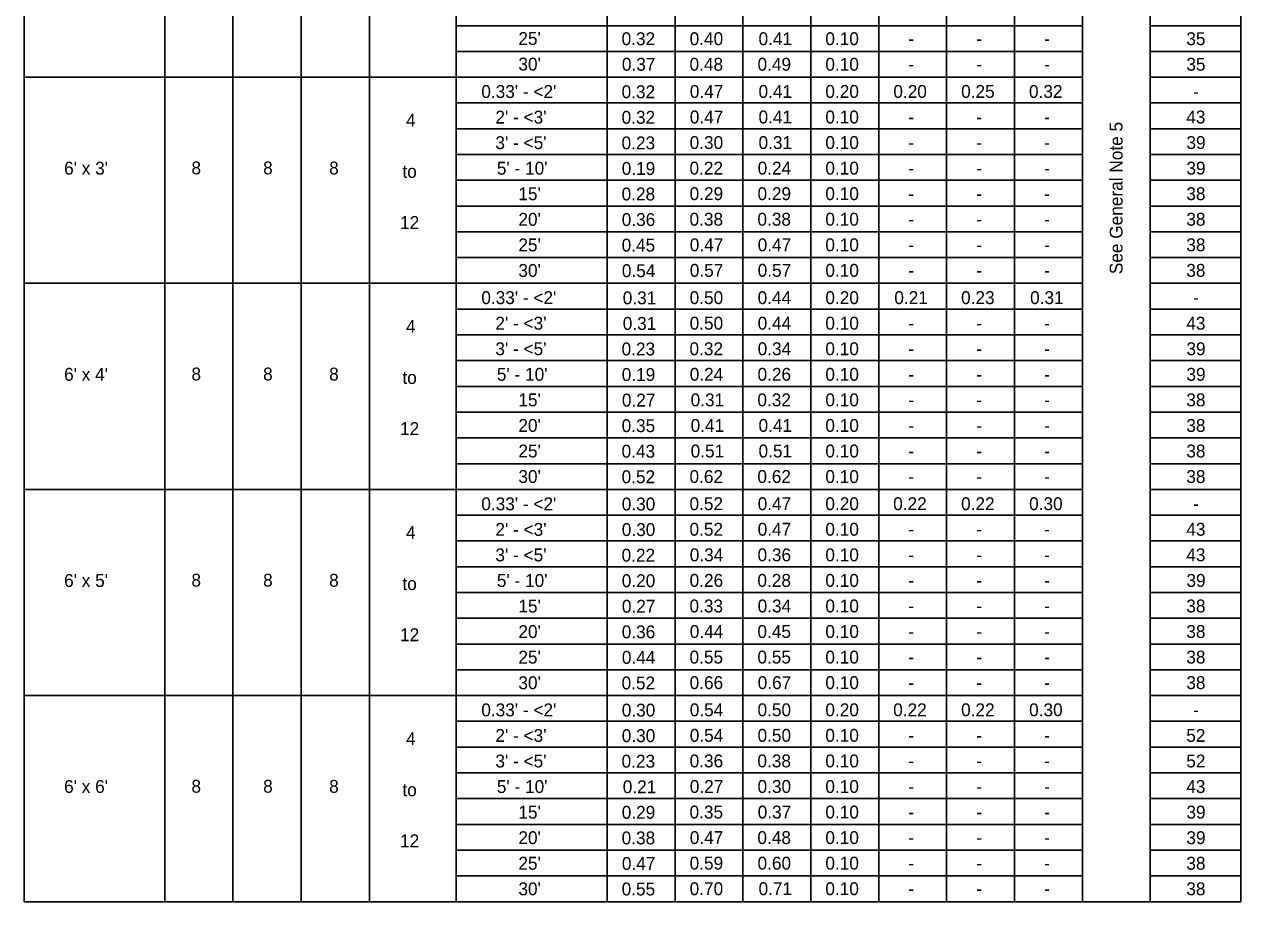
# Model space of a CAD drawing. Extents: x 10340.93 to 10343.14, y 76399.51 to 76400.59.
# Drawn here: x 10341.579 to 10342.173, y 76399.724 to 76400.153 of the extents above; entities that cross this region are included whole.
import ezdxf

# ---------------------------------------------------------------- set-up
doc = ezdxf.new("R2010")
doc.units = 0
doc.layers.add('AdhocPoint_dp', color=7, linetype='Continuous')
doc.layers.add('PlotBorder_dp', color=7, linetype='Continuous')

msp = doc.modelspace()

# ---------------------------------------------------------------- linework, layer by layer
at = {"layer": 'PlotBorder_dp'}
for p, q in [((10341.57868, 76400.49971), (10341.57868, 76399.72389)), ((10342.17342, 76400.49971), (10342.17342, 76399.72389)), ((10341.64732, 76400.47984), (10341.64732, 76399.72389)), ((10341.78976, 76400.47984), (10341.78976, 76399.72389)), ((10341.86364, 76400.47984), (10341.86364, 76399.72389)), ((10342.12923, 76400.47984), (10342.12923, 76399.72389)), ((10341.68068, 76400.46724), (10341.68068, 76399.72389)), ((10341.71404, 76400.46724), (10341.71404, 76399.72389)), ((10341.7474, 76400.46724), (10341.7474, 76399.72389)), ((10341.89684, 76400.44209), (10341.89684, 76399.72389)), ((10341.93004, 76400.44209), (10341.93004, 76399.72389)), ((10341.96324, 76400.44209), (10341.96324, 76399.72389)), ((10341.99644, 76400.44209), (10341.99644, 76399.72389)), ((10342.02963, 76400.44209), (10342.02963, 76399.72389)), ((10342.02963, 76400.44209), (10342.02963, 76399.72389)), ((10342.06283, 76400.44209), (10342.06283, 76399.72389)), ((10342.09603, 76400.44209), (10342.09603, 76399.72389)), ((10341.78976, 76400.15229), (10342.09603, 76400.15229)), ((10342.12923, 76400.15229), (10342.17342, 76400.15229)), ((10341.78976, 76400.13969), (10342.09603, 76400.13969)), ((10342.12923, 76400.13969), (10342.17342, 76400.13969)), ((10341.57868, 76400.12709), (10342.09603, 76400.12709)), ((10342.12923, 76400.12709), (10342.17342, 76400.12709)), ((10341.78976, 76400.11449), (10342.09603, 76400.11449)), ((10342.12923, 76400.11449), (10342.17342, 76400.11449)), ((10341.78976, 76400.10189), (10342.09603, 76400.10189)), ((10342.12923, 76400.10189), (10342.17342, 76400.10189)), ((10341.78976, 76400.08929), (10342.09603, 76400.08929)), ((10342.12923, 76400.08929), (10342.17342, 76400.08929)), ((10341.78976, 76400.07669), (10342.09603, 76400.07669)), ((10342.12923, 76400.07669), (10342.17342, 76400.07669)), ((10341.78976, 76400.06409), (10342.09603, 76400.06409)), ((10342.12923, 76400.06409), (10342.17342, 76400.06409)), ((10341.78976, 76400.05149), (10342.09603, 76400.05149)), ((10342.12923, 76400.05149), (10342.17342, 76400.05149)), ((10341.78976, 76400.03889), (10342.09603, 76400.03889)), ((10342.12923, 76400.03889), (10342.17342, 76400.03889)), ((10341.57868, 76400.02629), (10342.09603, 76400.02629)), ((10341.79037, 76400.02629), (10341.86254, 76400.02629)), ((10342.12923, 76400.02629), (10342.17342, 76400.02629)), ((10341.78976, 76400.01369), (10342.09603, 76400.01369)), ((10342.12923, 76400.01369), (10342.17342, 76400.01369)), ((10341.78976, 76400.00109), (10342.09603, 76400.00109)), ((10342.12923, 76400.00109), (10342.17342, 76400.00109)), ((10341.78976, 76399.98849), (10342.09603, 76399.98849)), ((10342.12923, 76399.98849), (10342.17342, 76399.98849)), ((10341.78976, 76399.97589), (10342.09603, 76399.97589)), ((10342.12923, 76399.97589), (10342.17342, 76399.97589)), ((10341.78976, 76399.96329), (10342.09603, 76399.96329)), ((10342.12923, 76399.96329), (10342.17342, 76399.96329)), ((10341.78976, 76399.95069), (10342.09603, 76399.95069)), ((10342.12923, 76399.95069), (10342.17342, 76399.95069)), ((10341.78976, 76399.93809), (10342.09603, 76399.93809)), ((10342.12923, 76399.93809), (10342.17342, 76399.93809)), ((10341.57868, 76399.92549), (10342.09603, 76399.92549)), ((10341.79037, 76399.92549), (10341.86254, 76399.92549)), ((10341.79037, 76399.92549), (10341.86254, 76399.92549)), ((10342.12923, 76399.92549), (10342.17342, 76399.92549)), ((10341.78976, 76399.91289), (10342.09603, 76399.91289)), ((10342.12923, 76399.91289), (10342.17342, 76399.91289)), ((10341.78976, 76399.90029), (10342.09603, 76399.90029)), ((10342.12923, 76399.90029), (10342.17342, 76399.90029)), ((10341.78976, 76399.88769), (10342.09603, 76399.88769)), ((10342.12923, 76399.88769), (10342.17342, 76399.88769)), ((10341.78976, 76399.87509), (10342.09603, 76399.87509)), ((10342.12923, 76399.87509), (10342.17342, 76399.87509)), ((10341.78976, 76399.86249), (10342.09603, 76399.86249)), ((10342.12923, 76399.86249), (10342.17342, 76399.86249)), ((10341.78976, 76399.84989), (10342.09603, 76399.84989)), ((10342.12923, 76399.84989), (10342.17342, 76399.84989)), ((10341.78976, 76399.83729), (10342.09603, 76399.83729)), ((10342.12923, 76399.83729), (10342.17342, 76399.83729)), ((10341.57868, 76399.82469), (10342.09603, 76399.82469)), ((10341.79037, 76399.82469), (10341.86254, 76399.82469)), ((10341.79037, 76399.82469), (10341.86254, 76399.82469)), ((10341.79037, 76399.82469), (10341.86254, 76399.82469)), ((10342.12923, 76399.82469), (10342.17342, 76399.82469)), ((10341.78976, 76399.81209), (10342.09603, 76399.81209)), ((10342.12923, 76399.81209), (10342.17342, 76399.81209)), ((10341.78976, 76399.79949), (10342.09603, 76399.79949)), ((10342.12923, 76399.79949), (10342.17342, 76399.79949)), ((10341.78976, 76399.78689), (10342.09603, 76399.78689)), ((10342.12923, 76399.78689), (10342.17342, 76399.78689)), ((10341.78976, 76399.77429), (10342.09603, 76399.77429)), ((10342.12923, 76399.77429), (10342.17342, 76399.77429)), ((10341.78976, 76399.76169), (10342.09603, 76399.76169)), ((10342.12923, 76399.76169), (10342.17342, 76399.76169)), ((10341.78976, 76399.74909), (10342.09603, 76399.74909)), ((10342.12923, 76399.74909), (10342.17342, 76399.74909)), ((10341.78976, 76399.73649), (10342.09603, 76399.73649)), ((10342.12923, 76399.73649), (10342.17342, 76399.73649)), ((10341.57868, 76399.72389), (10342.17342, 76399.72389)), ((10341.79037, 76399.72389), (10341.86254, 76399.72389))]:
    msp.add_line(p, q, dxfattribs=at)

# ---------------------------------------------------------------- texts
at = {"layer": 'AdhocPoint_dp'}
msp.add_text('See General Note 5', height=0.0063, rotation=90, dxfattribs=at).set_placement((10342.11568, 76400.03076))
at = {"layer": 'PlotBorder_dp'}
for s, p in [("25'", (10341.82025, 76400.14286)), ('0.32', (10341.87072, 76400.14276)), ('0.40', (10341.90399, 76400.14276)), ('0.41', (10341.93768, 76400.14276)), ('0.10', (10341.97035, 76400.14276)), ('-', (10342.01091, 76400.14276)), ('-', (10342.04412, 76400.14276)), ('-', (10342.0773, 76400.14276)), ('35', (10342.14685, 76400.14276)), ("30'", (10341.82025, 76400.13036)), ('0.37', (10341.87086, 76400.13026)), ('0.48', (10341.90393, 76400.13026)), ('0.49', (10341.93718, 76400.13026)), ('0.10', (10341.97035, 76400.13026)), ('-', (10342.01091, 76400.13026)), ('-', (10342.04412, 76400.13026)), ('-', (10342.0773, 76400.13026)), ('35', (10342.14685, 76400.13026)), ("0.33' - <2'", (10341.80212, 76400.11693)), ('0.32', (10341.87072, 76400.11682)), ('0.47', (10341.90406, 76400.11698)), ('0.41', (10341.93768, 76400.11698)), ('0.20', (10341.97035, 76400.11698)), ('0.20', (10342.00358, 76400.11698)), ('0.25', (10342.03674, 76400.11698)), ('0.32', (10342.0699, 76400.11698)), ('-', (10342.15015, 76400.11698)), ('4', (10341.76534, 76400.10289)), ("2' - <3'", (10341.80901, 76400.10443)), ('0.32', (10341.87072, 76400.10432)), ('0.47', (10341.90406, 76400.10448)), ('0.41', (10341.93768, 76400.10448)), ('0.10', (10341.97035, 76400.10448)), ('43', (10342.14682, 76400.10448)), ('-', (10342.01091, 76400.10448)), ('-', (10342.04412, 76400.10448)), ('-', (10342.0773, 76400.10448)), ("3' - <5'", (10341.80901, 76400.09193)), ('0.23', (10341.87071, 76400.09182)), ('0.30', (10341.90399, 76400.09198)), ('0.31', (10341.93768, 76400.09198)), ('0.10', (10341.97035, 76400.09198)), ('39', (10342.14689, 76400.09198)), ('-', (10342.01091, 76400.09198)), ('-', (10342.04412, 76400.09198)), ('-', (10342.0773, 76400.09198)), ("6' x 3'", (10341.59812, 76400.07943)), ('8', (10341.66039, 76400.07958)), ('8', (10341.69543, 76400.07958)), ('8', (10341.72772, 76400.07953)), ("5' - 10'", (10341.80973, 76400.07943)), ('0.19', (10341.87078, 76400.07932)), ('0.22', (10341.90392, 76400.07948)), ('0.24', (10341.93724, 76400.07948)), ('0.10', (10341.97035, 76400.07948)), ('39', (10342.14689, 76400.07948)), ('to', (10341.76356, 76400.07789)), ('-', (10342.01091, 76400.07948)), ('-', (10342.04412, 76400.07948)), ('-', (10342.0773, 76400.07948)), ("15'", (10341.82025, 76400.06693)), ('0.28', (10341.87073, 76400.06682)), ('0.29', (10341.90398, 76400.06698)), ('0.29', (10341.93718, 76400.06698)), ('0.10', (10341.97035, 76400.06698)), ('38', (10342.14684, 76400.06698)), ('-', (10342.01091, 76400.06698)), ('-', (10342.04412, 76400.06698)), ('-', (10342.0773, 76400.06698)), ("20'", (10341.82025, 76400.05443)), ('0.36', (10341.87078, 76400.05432)), ('0.38', (10341.90393, 76400.05448)), ('0.38', (10341.93713, 76400.05448)), ('0.10', (10341.97035, 76400.05448)), ('38', (10342.14684, 76400.05448)), ('12', (10341.76239, 76400.05289)), ('-', (10342.01091, 76400.05448)), ('-', (10342.04412, 76400.05448)), ('-', (10342.0773, 76400.05448)), ("25'", (10341.82025, 76400.04193)), ('0.45', (10341.87074, 76400.04182)), ('0.47', (10341.90406, 76400.04198)), ('0.47', (10341.93726, 76400.04198)), ('0.10', (10341.97035, 76400.04198)), ('-', (10342.01091, 76400.04198)), ('-', (10342.04412, 76400.04198)), ('-', (10342.0773, 76400.04198)), ('38', (10342.14684, 76400.04198)), ("30'", (10341.82025, 76400.02943)), ('0.54', (10341.87084, 76400.02932)), ('0.57', (10341.90406, 76400.02948)), ('0.57', (10341.93726, 76400.02948)), ('0.10', (10341.97035, 76400.02948)), ('-', (10342.01091, 76400.02948)), ('-', (10342.04412, 76400.02948)), ('-', (10342.0773, 76400.02948)), ('38', (10342.14684, 76400.02948)), ("0.33' - <2'", (10341.80212, 76400.01614)), ('0.31', (10341.87128, 76400.01604)), ('0.50', (10341.90399, 76400.01614)), ('0.44', (10341.93724, 76400.01614)), ('0.20', (10341.97035, 76400.01614)), ('0.21', (10342.00407, 76400.01614)), ('0.23', (10342.03671, 76400.01614)), ('0.31', (10342.07047, 76400.01614)), ('-', (10342.15015, 76400.01614)), ('4', (10341.76534, 76400.00209)), ("2' - <3'", (10341.80901, 76400.00364)), ('0.31', (10341.87128, 76400.00354)), ('0.50', (10341.90399, 76400.00364)), ('0.44', (10341.93724, 76400.00364)), ('0.10', (10341.97035, 76400.00364)), ('43', (10342.14682, 76400.00364)), ('-', (10342.01091, 76400.00364)), ('-', (10342.04412, 76400.00364)), ('-', (10342.0773, 76400.00364)), ("3' - <5'", (10341.80901, 76399.99114)), ('0.23', (10341.87071, 76399.99104)), ('0.32', (10341.90392, 76399.99114)), ('0.34', (10341.93724, 76399.99114)), ('0.10', (10341.97035, 76399.99114)), ('39', (10342.14689, 76399.99114)), ('-', (10342.01091, 76399.99114)), ('-', (10342.04412, 76399.99114)), ('-', (10342.0773, 76399.99114)), ("6' x 4'", (10341.59812, 76399.97864)), ('8', (10341.66039, 76399.9788)), ('8', (10341.69543, 76399.9788)), ('8', (10341.72772, 76399.97875)), ("5' - 10'", (10341.80973, 76399.97864)), ('0.19', (10341.87078, 76399.97854)), ('0.24', (10341.90404, 76399.97864)), ('0.26', (10341.93718, 76399.97864)), ('0.10', (10341.97035, 76399.97864)), ('39', (10342.14689, 76399.97864)), ('to', (10341.76356, 76399.97709)), ('-', (10342.01091, 76399.97864)), ('-', (10342.04412, 76399.97864)), ('-', (10342.0773, 76399.97864)), ("15'", (10341.82025, 76399.96614)), ('0.27', (10341.87086, 76399.96604)), ('0.31', (10341.90448, 76399.96614)), ('0.32', (10341.93712, 76399.96614)), ('0.10', (10341.97035, 76399.96614)), ('38', (10342.14684, 76399.96614)), ('-', (10342.01091, 76399.96614)), ('-', (10342.04412, 76399.96614)), ('-', (10342.0773, 76399.96614)), ("20'", (10341.82025, 76399.95364)), ('0.35', (10341.87074, 76399.95354)), ('0.41', (10341.90448, 76399.95364)), ('0.41', (10341.93768, 76399.95364)), ('0.10', (10341.97035, 76399.95364)), ('38', (10342.14684, 76399.95364)), ('12', (10341.76239, 76399.95209)), ('-', (10342.01091, 76399.95364)), ('-', (10342.04412, 76399.95364)), ('-', (10342.0773, 76399.95364)), ("25'", (10341.82025, 76399.94114)), ('0.43', (10341.87071, 76399.94104)), ('0.51', (10341.90448, 76399.94114)), ('0.51', (10341.93768, 76399.94114)), ('0.10', (10341.97035, 76399.94114)), ('-', (10342.01091, 76399.94114)), ('-', (10342.04412, 76399.94114)), ('-', (10342.0773, 76399.94114)), ('38', (10342.14684, 76399.94114)), ("30'", (10341.82025, 76399.92864)), ('0.52', (10341.87072, 76399.92854)), ('0.62', (10341.90392, 76399.92864)), ('0.62', (10341.93712, 76399.92864)), ('0.10', (10341.97035, 76399.92864)), ('-', (10342.01091, 76399.92864)), ('-', (10342.04412, 76399.92864)), ('-', (10342.0773, 76399.92864)), ('38', (10342.14684, 76399.92864)), ("0.33' - <2'", (10341.80212, 76399.91531)), ('0.30', (10341.8708, 76399.91521)), ('0.52', (10341.90392, 76399.91536)), ('0.47', (10341.93726, 76399.91536)), ('0.20', (10341.97035, 76399.91536)), ('0.22', (10342.00351, 76399.91536)), ('0.22', (10342.03671, 76399.91536)), ('0.30', (10342.06998, 76399.91536)), ('-', (10342.15015, 76399.91536)), ('4', (10341.76534, 76399.90129)), ("2' - <3'", (10341.80901, 76399.90281)), ('0.30', (10341.8708, 76399.90271)), ('0.52', (10341.90392, 76399.90286)), ('0.47', (10341.93726, 76399.90286)), ('0.10', (10341.97035, 76399.90286)), ('43', (10342.14682, 76399.90286)), ('-', (10342.01091, 76399.90286)), ('-', (10342.04412, 76399.90286)), ('-', (10342.0773, 76399.90286)), ("3' - <5'", (10341.80901, 76399.89031)), ('0.22', (10341.87072, 76399.89021)), ('0.34', (10341.90404, 76399.89036)), ('0.36', (10341.93718, 76399.89036)), ('0.10', (10341.97035, 76399.89036)), ('43', (10342.14682, 76399.89036)), ('-', (10342.01091, 76399.89036)), ('-', (10342.04412, 76399.89036)), ('-', (10342.0773, 76399.89036)), ("6' x 5'", (10341.59812, 76399.87781)), ('8', (10341.66039, 76399.87797)), ('8', (10341.69543, 76399.87797)), ('8', (10341.72772, 76399.87792)), ("5' - 10'", (10341.80973, 76399.87781)), ('0.20', (10341.8708, 76399.87771)), ('0.26', (10341.90398, 76399.87786)), ('0.28', (10341.93713, 76399.87786)), ('0.10', (10341.97035, 76399.87786)), ('39', (10342.14689, 76399.87786)), ('to', (10341.76356, 76399.87629)), ('-', (10342.01091, 76399.87786)), ('-', (10342.04412, 76399.87786)), ('-', (10342.0773, 76399.87786)), ("15'", (10341.82025, 76399.86531)), ('0.27', (10341.87086, 76399.86521)), ('0.33', (10341.90391, 76399.86536)), ('0.34', (10341.93724, 76399.86536)), ('0.10', (10341.97035, 76399.86536)), ('38', (10342.14684, 76399.86536)), ('-', (10342.01091, 76399.86536)), ('-', (10342.04412, 76399.86536)), ('-', (10342.0773, 76399.86536)), ("20'", (10341.82025, 76399.85281)), ('0.36', (10341.87078, 76399.85271)), ('0.44', (10341.90404, 76399.85286)), ('0.45', (10341.93714, 76399.85286)), ('0.10', (10341.97035, 76399.85286)), ('38', (10342.14684, 76399.85286)), ('12', (10341.76239, 76399.85129)), ('-', (10342.01091, 76399.85286)), ('-', (10342.04412, 76399.85286)), ('-', (10342.0773, 76399.85286)), ("25'", (10341.82025, 76399.84031)), ('0.55', (10341.90394, 76399.84036)), ('0.55', (10341.93714, 76399.84036)), ('0.10', (10341.97035, 76399.84036)), ('38', (10342.14684, 76399.84036)), ('0.44', (10341.87084, 76399.84021)), ('-', (10342.01091, 76399.84036)), ('-', (10342.04412, 76399.84036)), ('-', (10342.0773, 76399.84036)), ("30'", (10341.82025, 76399.82781)), ('0.52', (10341.87072, 76399.82771)), ('0.66', (10341.90398, 76399.82786)), ('0.67', (10341.93726, 76399.82786)), ('0.10', (10341.97035, 76399.82786)), ('-', (10342.01091, 76399.82786)), ('-', (10342.04412, 76399.82786)), ('-', (10342.0773, 76399.82786)), ('38', (10342.14684, 76399.82786)), ("0.33' - <2'", (10341.80212, 76399.81453)), ('0.30', (10341.8708, 76399.81443)), ('0.54', (10341.90404, 76399.81458)), ('0.50', (10341.93719, 76399.81458)), ('0.20', (10341.97035, 76399.81458)), ('0.22', (10342.00351, 76399.81458)), ('0.22', (10342.03671, 76399.81458)), ('0.30', (10342.06998, 76399.81458)), ('-', (10342.15015, 76399.81453)), ('4', (10341.76534, 76399.80049)), ("2' - <3'", (10341.80901, 76399.80203)), ('0.30', (10341.8708, 76399.80193)), ('0.54', (10341.90404, 76399.80208)), ('0.50', (10341.93719, 76399.80208)), ('0.10', (10341.97035, 76399.80208)), ('52', (10342.14682, 76399.80203)), ('-', (10342.01091, 76399.80208)), ('-', (10342.04412, 76399.80208)), ('-', (10342.0773, 76399.80208)), ("3' - <5'", (10341.80901, 76399.78953)), ('0.23', (10341.87071, 76399.78943)), ('0.36', (10341.90398, 76399.78958)), ('0.38', (10341.93713, 76399.78958)), ('0.10', (10341.97035, 76399.78958)), ('52', (10342.14682, 76399.78953)), ('-', (10342.01091, 76399.78958)), ('-', (10342.04412, 76399.78958)), ('-', (10342.0773, 76399.78958)), ("6' x 6'", (10341.59812, 76399.77708)), ('8', (10341.66039, 76399.77719)), ('8', (10341.69543, 76399.77719)), ('8', (10341.72772, 76399.77713)), ('to', (10341.76356, 76399.77549)), ("5' - 10'", (10341.80973, 76399.77703)), ('0.21', (10341.87128, 76399.77693)), ('0.27', (10341.90406, 76399.77708)), ('0.30', (10341.93719, 76399.77708)), ('0.10', (10341.97035, 76399.77708)), ('43', (10342.14682, 76399.77703)), ('-', (10342.01091, 76399.77708)), ('-', (10342.04412, 76399.77708)), ('-', (10342.0773, 76399.77708)), ("15'", (10341.82025, 76399.76453)), ('0.29', (10341.87078, 76399.76443)), ('0.35', (10341.90394, 76399.76458)), ('0.37', (10341.93726, 76399.76458)), ('0.10', (10341.97035, 76399.76458)), ('39', (10342.14689, 76399.76453)), ('-', (10342.01091, 76399.76458)), ('-', (10342.04412, 76399.76458)), ('-', (10342.0773, 76399.76458)), ("20'", (10341.82025, 76399.75203)), ('0.38', (10341.87073, 76399.75193)), ('0.47', (10341.90406, 76399.75208)), ('0.48', (10341.93713, 76399.75208)), ('0.10', (10341.97035, 76399.75208)), ('39', (10342.14689, 76399.75203)), ('12', (10341.76239, 76399.75049)), ('-', (10342.01091, 76399.75208)), ('-', (10342.04412, 76399.75208)), ('-', (10342.0773, 76399.75208)), ("25'", (10341.82025, 76399.73953)), ('0.47', (10341.87086, 76399.73943)), ('0.59', (10341.90398, 76399.73958)), ('0.60', (10341.93719, 76399.73958)), ('0.10', (10341.97035, 76399.73958)), ('38', (10342.14684, 76399.73953)), ('-', (10342.01091, 76399.73958)), ('-', (10342.04412, 76399.73958)), ('-', (10342.0773, 76399.73958)), ("30'", (10341.82025, 76399.72703)), ('0.55', (10341.87074, 76399.72693)), ('0.70', (10341.90399, 76399.72708)), ('0.71', (10341.93768, 76399.72708)), ('0.10', (10341.97035, 76399.72708)), ('-', (10342.01091, 76399.72708)), ('-', (10342.04412, 76399.72708)), ('-', (10342.0773, 76399.72708)), ('38', (10342.14684, 76399.72703))]:
    msp.add_text(s, height=0.0063, dxfattribs=at).set_placement(p)

doc.saveas('drawing.dxf')
